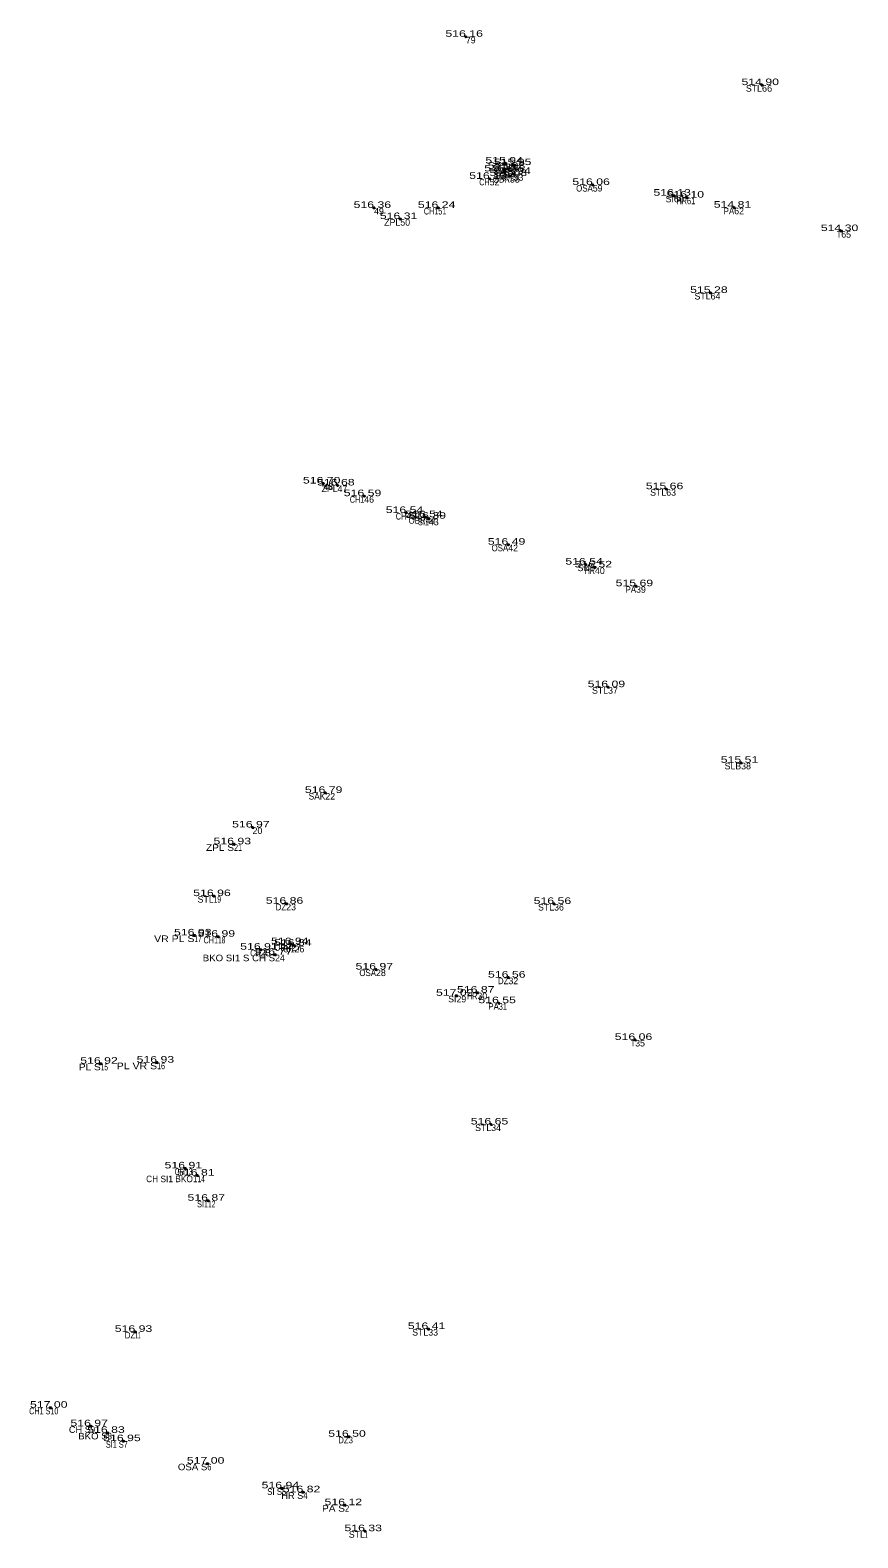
# Model space of a CAD drawing. Extents: x -643086 to -639283, y -1131805 to -1123269.
# Drawn here: x -639392.5 to -639354.7, y -1123844 to -1123775 of the extents above; entities that cross this region are included whole.
import ezdxf
from ezdxf.enums import TextEntityAlignment as Align

# ---------------------------------------------------------------- set-up
doc = ezdxf.new("R2010")
doc.units = 0
doc.header["$LTSCALE"] = 0.12
doc.header["$PDMODE"] = 32
doc.header["$PDSIZE"] = 0.06
for name, color, linetype in [('1', 7, 'Continuous'), ('2', 7, 'Continuous'), ('3', 7, 'Continuous'), ('4', 7, 'Continuous')]:
    doc.layers.add(name, color=color, linetype=linetype)

msp = doc.modelspace()

# ---------------------------------------------------------------- linework, layer by layer
at = {"layer": '1'}
for p in [(-639372.6, -1123775.3), (-639359.05, -1123777.51), (-639370.82, -1123781.46), (-639370.77, -1123781.1), (-639370.66, -1123781.34), (-639370.41, -1123781.58), (-639370.38, -1123781.17), (-639371.51, -1123781.8), (-639370.58, -1123781.67), (-639366.79, -1123782.08), (-639363.08, -1123782.57), (-639362.48, -1123782.66), (-639376.8, -1123783.13), (-639375.6, -1123783.64), (-639373.86, -1123783.13), (-639360.32, -1123783.12), (-639355.42, -1123784.19), (-639361.4, -1123787.02), (-639379.12, -1123795.74), (-639378.47, -1123795.83), (-639363.43, -1123796), (-639377.25, -1123796.32), (-639375.33, -1123797.09), (-639374.44, -1123797.28), (-639374.29, -1123797.35), (-639370.66, -1123798.54), (-639367.11, -1123799.45), (-639366.69, -1123799.58), (-639364.81, -1123800.44), (-639366.09, -1123805.06), (-639360, -1123808.52), (-639379.03, -1123809.9), (-639382.36, -1123811.48), (-639383.21, -1123812.25), (-639384.14, -1123814.62), (-639380.82, -1123814.97), (-639368.56, -1123814.98), (-639385.02, -1123816.42), (-639383.94, -1123816.48), (-639381.99, -1123817.07), (-639381.33, -1123817.3), (-639380.58, -1123816.82), (-639380.44, -1123816.89), (-639376.71, -1123817.98), (-639370.65, -1123818.35), (-639373.03, -1123819.18), (-639372.07, -1123819.04), (-639371.09, -1123819.52), (-639364.85, -1123821.2), (-639389.31, -1123822.29), (-639386.73, -1123822.24), (-639371.44, -1123825.07), (-639385.45, -1123827.08), (-639384.88, -1123827.41), (-639384.4, -1123828.56), (-639387.73, -1123834.56), (-639374.32, -1123834.43), (-639391.61, -1123838.03), (-639389.76, -1123838.88), (-639388.99, -1123839.18), (-639377.96, -1123839.36), (-639388.26, -1123839.56), (-639384.43, -1123840.59), (-639381.01, -1123841.72), (-639380.04, -1123841.9), (-639378.13, -1123842.49), (-639377.22, -1123843.68)]:
    msp.add_point(p, dxfattribs=at)

# ---------------------------------------------------------------- texts
at = {"layer": '2'}
for s, p in [('79', (-639372.6, -1123775.6)), ('54', (-639370.82, -1123781.76)), ('55', (-639370.77, -1123781.4)), ('57', (-639370.66, -1123781.64)), ('56', (-639370.38, -1123781.47)), ('52', (-639371.51, -1123782.1)), ('58', (-639370.58, -1123781.97)), ('53', (-639370.41, -1123781.88)), ('59', (-639366.79, -1123782.38)), ('49', (-639376.8, -1123783.43)), ('62', (-639360.32, -1123783.42)), ('50', (-639375.6, -1123783.94)), ('65', (-639355.42, -1123784.49)), ('64', (-639361.4, -1123787.32)), ('48', (-639379.12, -1123796.04)), ('47', (-639378.47, -1123796.13)), ('63', (-639363.43, -1123796.3)), ('46', (-639377.25, -1123796.62)), ('45', (-639375.33, -1123797.39)), ('44', (-639374.44, -1123797.58)), ('43', (-639374.29, -1123797.65)), ('42', (-639370.66, -1123798.84)), ('40', (-639366.69, -1123799.88)), ('39', (-639364.81, -1123800.74)), ('37', (-639366.09, -1123805.36)), ('38', (-639360, -1123808.82)), ('22', (-639379.03, -1123810.2)), ('20', (-639382.36, -1123811.78)), ('23', (-639380.82, -1123815.27)), ('36', (-639368.56, -1123815.28)), ('25', (-639381.99, -1123817.37)), ('24', (-639381.33, -1123817.6)), ('27', (-639380.58, -1123817.12)), ('26', (-639380.44, -1123817.19)), ('28', (-639376.71, -1123818.28)), ('32', (-639370.65, -1123818.65)), ('29', (-639373.03, -1123819.48)), ('30', (-639372.07, -1123819.34)), ('35', (-639364.85, -1123821.5)), ('34', (-639371.44, -1123825.37)), ('33', (-639374.32, -1123834.73))]:
    msp.add_text(s, height=0.3, dxfattribs=at).set_placement(p)
for s, width, p in [('66', 1.05, (-639359.05, -1123777.81)), ('60', 1.05, (-639363.08, -1123782.87)), ('61', 0.85, (-639362.48, -1123782.96)), ('51', 0.8, (-639373.86, -1123783.43)), ('41', 0.8, (-639367.11, -1123799.75)), ('21', 0.8, (-639383.21, -1123812.55)), ('19', 0.6, (-639384.14, -1123814.92)), ('17', 0.6, (-639385.02, -1123816.72)), ('18', 0.6, (-639383.94, -1123816.78)), ('31', 0.8, (-639371.09, -1123819.82)), ('16', 0.65, (-639386.73, -1123822.54)), ('15', 0.6, (-639389.31, -1123822.59)), ('13', 0.6, (-639385.45, -1123827.38)), ('14', 0.6, (-639384.88, -1123827.71)), ('12', 0.6, (-639384.4, -1123828.86)), ('11', 0.45, (-639387.73, -1123834.86)), ('10', 0.65, (-639391.61, -1123838.33)), ('9', 0.75, (-639389.76, -1123839.18)), ('8', 0.75, (-639388.99, -1123839.48)), ('3', 0.75, (-639377.96, -1123839.66)), ('7', 0.75, (-639388.26, -1123839.86)), ('6', 0.85, (-639384.43, -1123840.89)), ('5', 0.75, (-639381.01, -1123842.02)), ('4', 0.75, (-639380.04, -1123842.2)), ('2', 0.75, (-639378.13, -1123842.79)), ('1', 0.45, (-639377.22, -1123843.98))]:
    msp.add_text(s, height=0.3, dxfattribs=dict(at, width=width)).set_placement(p)
at = {"layer": '3', "width": 1.4}
for s, p in [('516 16 ', (-639372.6, -1123775.3)), ('514 90 ', (-639359.05, -1123777.51)), ('515 94 ', (-639370.77, -1123781.1)), ('515 95 ', (-639370.38, -1123781.17)), ('516 13 ', (-639371.51, -1123781.8)), ('515 97 ', (-639370.82, -1123781.46)), ('515 93 ', (-639370.66, -1123781.34)), ('516 08 ', (-639370.58, -1123781.67)), ('515 94 ', (-639370.41, -1123781.58)), ('516 06 ', (-639366.79, -1123782.08)), ('516 36 ', (-639376.8, -1123783.13)), ('516 24 ', (-639373.86, -1123783.13)), ('516 13 ', (-639363.08, -1123782.57)), ('516 10 ', (-639362.48, -1123782.66)), ('514 81 ', (-639360.32, -1123783.12)), ('516 31 ', (-639375.6, -1123783.64)), ('514 30 ', (-639355.42, -1123784.19)), ('515 28 ', (-639361.4, -1123787.02)), ('516 70 ', (-639379.12, -1123795.74)), ('516 68 ', (-639378.47, -1123795.83)), ('516 59 ', (-639377.25, -1123796.32)), ('515 66 ', (-639363.43, -1123796)), ('516 54 ', (-639375.33, -1123797.09)), ('516 54 ', (-639374.44, -1123797.28)), ('516 39 ', (-639374.29, -1123797.35)), ('516 49 ', (-639370.66, -1123798.54)), ('516 54 ', (-639367.11, -1123799.45)), ('516 52 ', (-639366.69, -1123799.58)), ('515 69 ', (-639364.81, -1123800.44)), ('516 09 ', (-639366.09, -1123805.06)), ('515 51 ', (-639360, -1123808.52)), ('516 79 ', (-639379.03, -1123809.9)), ('516 97 ', (-639382.36, -1123811.48)), ('516 93 ', (-639383.21, -1123812.25)), ('516 96 ', (-639384.14, -1123814.62)), ('516 86 ', (-639380.82, -1123814.97)), ('516 56 ', (-639368.56, -1123814.98)), ('516 93 ', (-639385.02, -1123816.42)), ('516 99 ', (-639383.94, -1123816.48)), ('516 94 ', (-639380.58, -1123816.82)), ('516 84 ', (-639380.44, -1123816.89)), ('516 91 ', (-639381.99, -1123817.07)), ('516 77 ', (-639381.33, -1123817.3)), ('516 97 ', (-639376.71, -1123817.98)), ('516 56 ', (-639370.65, -1123818.35)), ('516 87 ', (-639372.07, -1123819.04)), ('517 02 ', (-639373.03, -1123819.18)), ('516 55 ', (-639371.09, -1123819.52)), ('516 06 ', (-639364.85, -1123821.2)), ('516 92 ', (-639389.31, -1123822.29)), ('516 93 ', (-639386.73, -1123822.24)), ('516 65 ', (-639371.44, -1123825.07)), ('516 91 ', (-639385.45, -1123827.08)), ('516 81 ', (-639384.88, -1123827.41)), ('516 87 ', (-639384.4, -1123828.56)), ('516 93 ', (-639387.73, -1123834.56)), ('516 41 ', (-639374.32, -1123834.43)), ('517 00 ', (-639391.61, -1123838.03)), ('516 97 ', (-639389.76, -1123838.88)), ('516 83 ', (-639388.99, -1123839.18)), ('516 95 ', (-639388.26, -1123839.56)), ('516 50 ', (-639377.96, -1123839.36)), ('517 00 ', (-639384.43, -1123840.59)), ('516 94 ', (-639381.01, -1123841.72)), ('516 82 ', (-639380.04, -1123841.9)), ('516 12 ', (-639378.13, -1123842.49)), ('516 33 ', (-639377.22, -1123843.68))]:
    msp.add_text(s, height=0.3, dxfattribs=at).set_placement(p, align=Align.CENTER)
at = {"layer": '4'}
for s, p in [('STL', (-639359.05, -1123777.81)), ('SI', (-639363.08, -1123782.87)), ('ZPL', (-639375.6, -1123783.94)), ('STL', (-639361.4, -1123787.32)), ('ZPL', (-639378.47, -1123796.13)), ('STL', (-639363.43, -1123796.3)), ('SI', (-639367.11, -1123799.75)), ('STL', (-639366.09, -1123805.36)), ('SLB', (-639360, -1123808.82)), ('STL', (-639384.14, -1123814.92)), ('STL', (-639368.56, -1123815.28)), ('SI', (-639373.03, -1123819.48)), ('STL', (-639371.44, -1123825.37)), ('STL', (-639374.32, -1123834.73)), ('STL', (-639377.22, -1123843.98))]:
    msp.add_text(s, height=0.3, dxfattribs=at).set_placement(p, align=Align.RIGHT)
for s, width, p in [('SI1', 0.8, (-639370.82, -1123781.76)), ('SI1', 0.8, (-639370.77, -1123781.4)), ('VP', 0.9, (-639370.66, -1123781.64)), ('SI1', 0.8, (-639370.38, -1123781.47)), ('CH', 0.8, (-639371.51, -1123782.1)), ('OBR', 0.9, (-639370.58, -1123781.97)), ('SI1', 0.8, (-639370.41, -1123781.88)), ('OSA', 0.9, (-639366.79, -1123782.38)), ('HR', 0.8, (-639362.48, -1123782.96)), ('CH1', 0.8, (-639373.86, -1123783.43)), ('PA', 0.9, (-639360.32, -1123783.42)), ('T', 0.8, (-639355.42, -1123784.49)), ('CH1', 0.8, (-639377.25, -1123796.62)), ('CH', 0.8, (-639375.33, -1123797.39)), ('OBR', 0.9, (-639374.44, -1123797.58)), ('SI1', 0.8, (-639374.29, -1123797.65)), ('OSA', 0.9, (-639370.66, -1123798.84)), ('HR', 0.8, (-639366.69, -1123799.88)), ('PA', 0.9, (-639364.81, -1123800.74)), ('SAK', 0.95, (-639379.03, -1123810.2)), ('ZPL S', 1.15, (-639383.21, -1123812.55)), ('DZ', 0.9, (-639380.82, -1123815.27)), ('VR PL S', 1.2, (-639385.02, -1123816.72)), ('CH1', 0.8, (-639383.94, -1123816.78)), ('BKO SI1 S CH S', 1.1, (-639381.33, -1123817.6)), ('CH', 0.8, (-639381.99, -1123817.37)), ('OBR', 0.9, (-639380.58, -1123817.12)), ('SI1', 0.8, (-639380.44, -1123817.19)), ('OSA', 0.9, (-639376.71, -1123818.28)), ('DZ', 0.9, (-639370.65, -1123818.65)), ('HR', 0.8, (-639372.07, -1123819.34)), ('PA', 0.9, (-639371.09, -1123819.82)), ('T', 0.8, (-639364.85, -1123821.5)), ('PL VR S', 1.2, (-639386.73, -1123822.54)), ('PL S', 1.15, (-639389.31, -1123822.59)), ('CH', 0.8, (-639385.45, -1123827.38)), ('CH SI1 BKO1', 0.95, (-639384.88, -1123827.71)), ('SI1', 0.8, (-639384.4, -1123828.86)), ('DZ', 0.9, (-639387.73, -1123834.86)), ('CH1 S', 0.8, (-639391.61, -1123838.33)), ('CH S', 1.05, (-639389.76, -1123839.18)), ('BKO S', 1.1, (-639388.99, -1123839.48)), ('DZ', 0.9, (-639377.96, -1123839.66)), ('SI1 S', 0.8, (-639388.26, -1123839.86)), ('OSA S', 1.1, (-639384.43, -1123840.89)), ('SI S', 0.9, (-639381.01, -1123842.02)), ('HR S', 1.05, (-639380.04, -1123842.2)), ('PA S', 1.15, (-639378.13, -1123842.79))]:
    msp.add_text(s, height=0.3, dxfattribs=dict(at, width=width)).set_placement(p, align=Align.RIGHT)

doc.saveas('drawing.dxf')
